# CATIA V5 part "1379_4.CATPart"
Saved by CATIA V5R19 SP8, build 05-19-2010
Part number: 4
Bounding box of the stored display mesh (mm): x -2.948 to 2.948, y 3.5 to 72.5, z -2.975 to 2.975
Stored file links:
  C:\Users\ThinkMotion\Desktop\EU_thinkMotion\iao\IAO_MMS_Groupe3\bblot\bblot\1379_4.CATPart
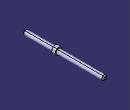
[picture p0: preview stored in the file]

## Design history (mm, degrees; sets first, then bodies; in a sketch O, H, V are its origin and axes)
Body1 (main body)
  Line1: stored without definition
  Line2: stored without definition
  Sketch1 on yz-plane, origin (0, 0, 0), H (0, 1, 0), V (0, 0, 1)
    axis line L1 (3.5, 0) -> (65.0512, 0)
    point P1 (3.5, 0)
    reference projected line E1 through (0, 0) direction (1, 0) from Line1
    line L2 (29.5, 3) -> (32.5, 3)
    line L3 (32.5, 3) -> (32.5, 2)
    line L4 (32.5, 2) -> (72.5, 2)
    point P7 (72.5, 0)
    line L5 (29.5, 2) -> (3.5, 2)
    point P10 (3.5, 0)
    line L6 (3.5, 0) -> (72.5, 0)
    point P11 (72.5, 0)
    line L7 (29.5, 2) -> (29.5, 3)
    line L8 (3.5, 2) -> (3.5, 0)
    point P12 (3.5, 0)
    line L9 (72.5, 2) -> (72.5, 0)
    reference projected line E2 through (0, 0) direction (0, 1) from Line2
    length L2 = 3
    distance L6 L2 = 3
    distance L4 L6 = 2
    distance L5 L6 = 2
    length L5 = 26
    distance L8 E2 = 3.5
    distance L9 L3 = 40
    horizontal: L1 H, L2 H, L4 H, L5 H
    coincidence: L1 E1, L6 P7, P7 P11, P1 P10, L6 L1, L8 P1, P12 L1
    vertical: L3 V, L7 V, L9 V, L8 V
  Shaft1: profile Sketch1, axis Sketch1.L1, angle 360
  Chamfer1: length 1, angle 45, on edge [face of Shaft1 from Sketch1.L4 | face of Shaft1 from Sketch1.L9]; edge [face of Shaft1 from Sketch1.L8 | face of Shaft1 from Sketch1.L5]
